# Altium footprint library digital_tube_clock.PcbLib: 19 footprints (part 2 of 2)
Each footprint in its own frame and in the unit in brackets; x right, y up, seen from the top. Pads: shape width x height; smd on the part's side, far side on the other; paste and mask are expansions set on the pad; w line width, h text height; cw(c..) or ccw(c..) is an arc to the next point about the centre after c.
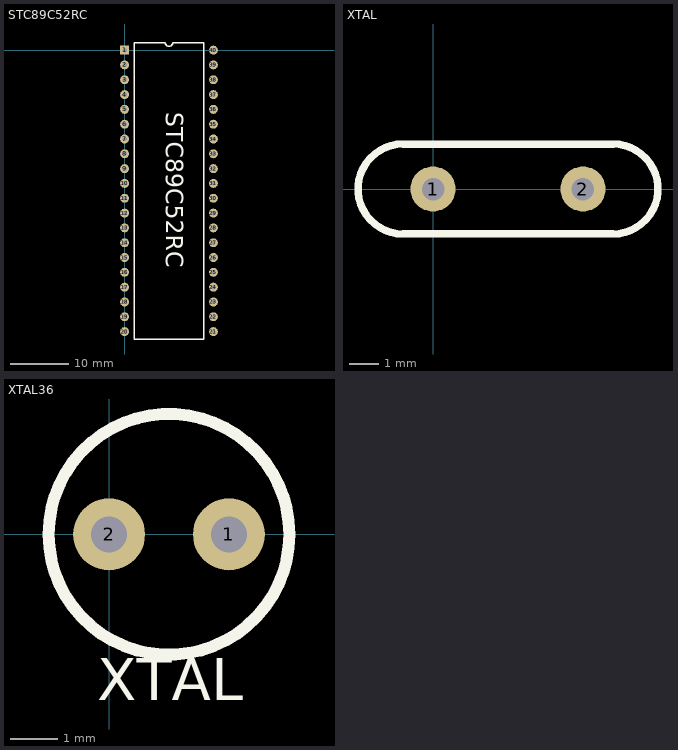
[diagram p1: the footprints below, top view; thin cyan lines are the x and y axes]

## STC89C52RC [mil]
pads (40):
  rect 60x60 / inner rect 60x6 / far side rect 60x60 hole 30: 1(0,0)
  round 60 / inner oval 60x6 / far side round 60 hole 30: 2(0,-100) 3(0,-200) 4(0,-300) 5(0,-400) 6(0,-500) 7(0,-600) 8(0,-700) 9(0,-800) 10(0,-900) 11(0,-1000) 12(0,-1100) 13(0,-1200) 14(0,-1300) 15(0,-1400) 16(0,-1500) 17(0,-1600) 18(0,-1700) 19(0,-1800) 20(0,-1900) 21(600,-1900) 22(600,-1800) 23(600,-1700) 24(600,-1600) 25(600,-1500) 26(600,-1400) 27(600,-1300) 28(600,-1200) 29(600,-1100) 30(600,-1000) 31(600,-900) 32(600,-800) 33(600,-700) 34(600,-600) 35(600,-500) 36(600,-400) 37(600,-300) 38(600,-200) 39(600,-100) 40(600,0)
Top Overlay:
  lines w10: 65,-1950 65,50 275,50 ccw(c300,50) 325,50 535,50 535,-1950 65,-1950
  text "STC89C52RC" at 240,-420 h200

## XTAL [mil]
pads (2):
  round 60 hole 30: 1(0,0) 2(200,0)
Top Overlay:
  lines w10: -40,-60 cw(c-40,0) -40,60 240,60 cw(c240,0) 240,-60 -40,-60

## XTAL36 [mil]
pads (2):
  round 60 hole 30: 1(100,0) 2(0,0)
Top Overlay:
  circle w10: c50,0 r100.5
  text "XTAL" at -10,-150 h60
